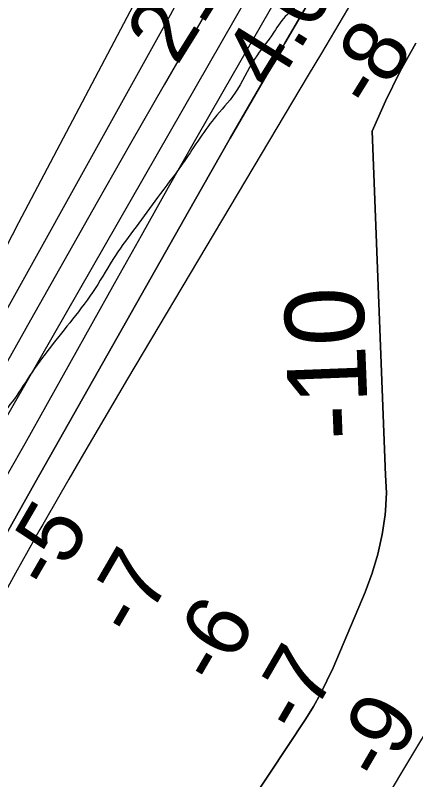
# Model space of a CAD drawing. Extents: x 3297735 to 3335592, y 670436 to 695807.
# Drawn here: x 3318935 to 3319354, y 692609 to 693409 of the extents above; entities that cross this region are included whole.
import ezdxf

# ---------------------------------------------------------------- set-up
doc = ezdxf.new("R2010")
doc.units = 0
for name, color, linetype in [('V-RIVR-EDGE', 7, 'Continuous'), ('V-RIVR-RANG', 7, 'Continuous'), ('V-TOPO-DPTH', 7, 'Continuous'), ('V-TOPO-MAJR', 7, 'Continuous'), ('V-TOPO-MINR', 7, 'Continuous'), ('V-TOPO-MINR-IDEN', 7, 'Continuous'), ('V-TOPO-WATR', 7, 'Continuous')]:
    doc.layers.add(name, color=color, linetype=linetype)

msp = doc.modelspace()

# ---------------------------------------------------------------- linework, layer by layer
at = {"layer": 'V-RIVR-EDGE'}
msp.add_spline([(3319555.14, 694014.55), (3319548.52, 694002.76), (3319539.36, 693985.79), (3319509.78, 693923.27), (3319496.46, 693903), (3319479.41, 693878.17), (3319464.01, 693854.58), (3319445.27, 693818.98), (3319424.44, 693775.51), (3319406.53, 693740.74), (3319395.69, 693713), (3319386.52, 693693.13), (3319372.79, 693671.61), (3319340.34, 693621.53), (3319316.61, 693580.14), (3319295.79, 693542.89), (3319282.06, 693520.96), (3319271.65, 693502.33), (3319267.89, 693489.49), (3319259.98, 693475.83), (3319250.42, 693465.08), (3319246.25, 693454.32), (3319237.93, 693442.32), (3319231.68, 693428.65), (3319225.43, 693414.99), (3319219.61, 693410.03), (3319205.47, 693391.42), (3319185.09, 693363.28), (3319164.7, 693327.69), (3319143.08, 693301.21), (3319109.39, 693253.21), (3319083.6, 693218.46), (3319061.14, 693187.85), (3319039.52, 693157.64), (3319018.29, 693123.29), (3318994.59, 693091.02), (3318949.68, 693031.86), (3318931.37, 693004.55), (3318913.08, 692981.38), (3318902.25, 692962.76), (3318892.68, 692944.55), (3318876.03, 692916.4), (3318861.86, 692887.84), (3318841.46, 692848.51), (3318822.29, 692807.53), (3318806.46, 692774.41), (3318803.1, 692758.66), (3318804.31, 692744.98), (3318808.02, 692734.61), (3318808.84, 692730.46), (3318817.11, 692725.47), (3318826.63, 692719.23), (3318832.83, 692713), (3318835.72, 692705.53), (3318835.27, 692692.27), (3318829.85, 692681.5), (3318819.88, 692669.09), (3318809.47, 692651.3), (3318783.24, 692602.87), (3318768.67, 692580.52), (3318760.79, 692575.98), (3318753.73, 692573.1), (3318747.11, 692573.94), (3318739.24, 692579.76), (3318735.53, 692585.58), (3318730.56, 692588.49), (3318721.44, 692588.1), (3318700.27, 692573.64), (3318679.48, 692549.66), (3318660.76, 692522.35), (3318646.6, 692493.37), (3318637.03, 692477.64), (3318624.96, 692456.95), (3318607.08, 692434.19), (3318599.98, 692413.49), (3318583.3, 692372.49), (3318565.82, 692342.28), (3318547.09, 692313.73), (3318534.2, 692295.52), (3318512.56, 692258.69), (3318488.02, 692224.76), (3318446.4, 692155.23), (3318418.11, 692112.61), (3318397.31, 692084.47), (3318386.91, 692066.68), (3318376.5, 692048.05), (3318354.44, 692011.22), (3318333.22, 691976.45), (3318316.13, 691940.02), (3318301.57, 691917.67), (3318275.38, 691884.99), (3318265.81, 691873), (3318250.82, 691844.85), (3318236.64, 691808.41), (3318222.07, 691781.09), (3318194.96, 691714.01), (3318179.96, 691684.2), (3318162.07, 691654.82), (3318140.84, 691619.64), (3318130.44, 691603.92), (3318120.89, 691595.24), (3318105.09, 691577.87), (3318090.12, 691558.42), (3318067.68, 691532.37), (3318043.56, 691501.75), (3318020.26, 691465.75), (3317998.21, 691433.06), (3317973.66, 691392.92), (3317962.42, 691371.81), (3317929.95, 691315.1), (3317907.9, 691282.41), (3317889.2, 691263.39), (3317870.48, 691238.16), (3317844.7, 691202.99), (3317833.05, 691186.02), (3317808.09, 691148.78), (3317780.64, 691109.47), (3317756.1, 691076.38), (3317731.98, 691045.35), (3317684.57, 690978.73), (3317668.76, 690954.73), (3317646.3, 690922.04), (3317635.48, 690907.15), (3317629.25, 690900.53), (3317620.1, 690889.36), (3317608.46, 690874.47), (3317601.4, 690867.03), (3317592.67, 690860.42), (3317585.59, 690845.93), (3317576.86, 690836), (3317565.64, 690821.11), (3317549.42, 690801.25), (3317522.4, 690767.75), (3317502.45, 690745), (3317489.97, 690727.62), (3317482.47, 690713.55), (3317479.54, 690701.12), (3317475.78, 690689.94), (3317474.94, 690683.31), (3317467.87, 690674.21), (3317451.65, 690653.94), (3317427.54, 690622.91), (3317406.33, 690593.95), (3317381.8, 690564.58), (3317328.18, 690504.62), (3317308.23, 690483.11), (3317290.78, 690466.16), (3317272.5, 690446.31), (3317248.81, 690422.74), (3317230.94, 690402.48), (3317202.23, 690356.54), (3317170.21, 690314.34), (3317129.47, 690266.36), (3317099.12, 690227.48), (3317085.82, 690212.59), (3317074.19, 690204.33), (3317063.38, 690189.85), (3317045.08, 690163.78), (3317020.95, 690128.61), (3316996.82, 690093.85), (3316970.63, 690059.1), (3316926.98, 690008.23), (3316891.65, 689970.6), (3316861.71, 689930.05), (3316828.03, 689887.86), (3316809.31, 689860.13), (3316797.25, 689841.93), (3316783.53, 689825.38), (3316737.37, 689762.08), (3316714.9, 689728.98), (3316681.64, 689687.61), (3316661.69, 689665.69), (3316647.97, 689646.66), (3316619.68, 689606.11), (3316602.63, 689581.28), (3316583.49, 689551.9), (3316563.93, 689519.62), (3316547.71, 689499.35), (3316541.89, 689491.9), (3316538.57, 689488.6), (3316532.31, 689474.1), (3316523.16, 689461.28), (3316509.03, 689445.15), (3316500.29, 689431.49), (3316493.22, 689419.9), (3316485.73, 689407.9), (3316486.11, 689397.12), (3316486.48, 689375.57), (3316487.29, 689371.01), (3316491.44, 689370.17), (3316493.5, 689366.43), (3316494.29, 689352.75), (3316496.75, 689341.56), (3316502.54, 689336.57), (3316504.2, 689334.08), (3316504.18, 689328.69), (3316501.27, 689325.8), (3316488.83, 689321.27), (3316487.17, 689319.61), (3316487.16, 689316.71), (3316492.96, 689316.7), (3316502.08, 689318.33), (3316508.3, 689318.32), (3316513.27, 689314.99), (3316516.58, 689314.98), (3316524.87, 689314.55), (3316535.62, 689303.33), (3316544.71, 689293.36), (3316545.54, 689290.04), (3316543.46, 689287.97), (3316525.66, 689296.72), (3316509.92, 689304.22), (3316502.06, 689307.14), (3316490.45, 689308.41), (3316482.58, 689308.02), (3316478.02, 689308.03), (3316473.47, 689311.77), (3316449.46, 689323.85), (3316424.59, 689324.74), (3316401.79, 689323.14), (3316381.47, 689318.22), (3316366.54, 689316.18), (3316352.85, 689311.24), (3316334.16, 689295.54), (3316302.2, 689277.79), (3316275.21, 689257.14), (3316266.49, 689249.28), (3316249.02, 689224.04), (3316230.28, 689191.76), (3316217.78, 689162.78), (3316200.69, 689125.93), (3316182.37, 689092.82), (3316162.8, 689054.73), (3316141.17, 689024.94), (3316114.57, 688996.41), (3316081.77, 688971.62), (3316036.89, 688926.14), (3316007.39, 688897.61), (3315987.04, 688880.67), (3315970.01, 688865.79), (3315959.63, 688858.77), (3315957.13, 688852.14), (3315955.46, 688848.42), (3315953.91, 688835.53)], degree=3, dxfattribs=at)
at = {"layer": 'V-TOPO-DPTH'}
for points in [[(3319397.53, 693802.93), (3319208.57, 693481.24), (3319197.61, 693462.51), (3319186.68, 693443.76), (3319175.8, 693424.98), (3319164.96, 693406.17), (3318890.81, 692929.09), (3318889.57, 692926.93), (3318887.11, 692922.6), (3318885.89, 692920.44), (3318883.86, 692916.84), (3318883.24, 692915.73), (3318881.62, 692912.8), (3318879.81, 692909.49), (3318878.9, 692907.83), (3318878, 692906.18), (3318861.29, 692875.47), (3318852.04, 692858.46), (3318842.79, 692841.44), (3318833.53, 692824.43), (3318824.28, 692807.42), (3318495.08, 692202.06)], [(3318762.29, 692573.01), (3318806.07, 692650.9), (3318849.52, 692728.97), (3318916.57, 692850.34), (3318926.28, 692867.85), (3318936.02, 692885.34), (3318945.82, 692902.8), (3318955.65, 692920.23), (3319122.05, 693214.3), (3319140.91, 693247.5), (3319159.83, 693280.66), (3319178.85, 693313.76), (3319197.95, 693346.82), (3319217.11, 693379.84), (3319236.3, 693412.85), (3319255.52, 693445.83), (3319274.77, 693478.8), (3319305.8, 693531.86), (3319340.53, 693591.37), (3319375.22, 693650.92)], [(3318762.29, 692573.01), (3318806.07, 692650.9), (3318849.52, 692728.97), (3318916.57, 692850.34), (3318926.28, 692867.85), (3318936.02, 692885.34), (3318945.82, 692902.8), (3318955.65, 692920.23), (3319122.05, 693214.3), (3319140.91, 693247.5), (3319159.83, 693280.66), (3319178.85, 693313.76), (3319197.95, 693346.82), (3319217.11, 693379.84), (3319236.3, 693412.85), (3319255.52, 693445.83), (3319274.77, 693478.8), (3319305.8, 693531.86), (3319340.53, 693591.37), (3319375.22, 693650.92)], [(3319143.8, 692528.91), (3319238.82, 692672.79), (3319246.83, 692685.67), (3319254.34, 692698.82), (3319261.12, 692712.36), (3319267.41, 692726.16), (3319300.94, 692805.49), (3319308.26, 692825.15), (3319314.4, 692845.12), (3319318.79, 692865.55), (3319322.01, 692886.29), (3319322.5, 692890.71), (3319323.27, 692909.31), (3319322.38, 692927.72), (3319308.3, 693288.04), (3319322.36, 693319.33), (3319337.46, 693350.07), (3319354.14, 693379.99)], [(3319354.14, 693379.99), (3319337.46, 693350.07), (3319322.36, 693319.33), (3319308.3, 693288.04), (3319322.38, 692927.72), (3319323.27, 692909.31), (3319322.5, 692890.71), (3319322.01, 692886.29), (3319318.79, 692865.55), (3319314.4, 692845.12), (3319308.26, 692825.15), (3319300.94, 692805.49), (3319267.41, 692726.16), (3319261.12, 692712.36), (3319254.34, 692698.82), (3319246.83, 692685.67), (3319238.82, 692672.79), (3319143.8, 692528.91)]]:
    msp.add_lwpolyline(points, dxfattribs=at)
at = {"layer": 'V-TOPO-MAJR'}
msp.add_lwpolyline([(3319313.56, 693852.85), (3319280.55, 693798.62), (3319123.25, 693537.44), (3319111.55, 693517.64), (3319100.09, 693497.72), (3319088.97, 693477.61), (3319078.07, 693457.37), (3318938.07, 693191.84), (3318917.38, 693152.67), (3318896.66, 693113.51), (3318875.91, 693074.37), (3318855.12, 693035.25), (3318822, 692973.01), (3318817.73, 692965.03), (3318813.44, 692957.06), (3318809.11, 692949.11), (3318804.75, 692941.17), (3318509.85, 692406.6)], dxfattribs=at)
at = {"layer": 'V-TOPO-MINR'}
for points in [[(3319458.23, 694014.45), (3319181.56, 693556.63), (3319173.57, 693543.32), (3319165.62, 693529.99), (3319157.74, 693516.62), (3319149.9, 693503.22), (3319136.82, 693480.7), (3319135.57, 693478.53), (3319133.09, 693474.19), (3319131.87, 693472.01), (3319119.33, 693449.58), (3319111.85, 693436.18), (3319104.37, 693422.78), (3319096.9, 693409.37), (3319089.43, 693395.96), (3318863.75, 692990.42), (3318850.58, 692966.73), (3318837.43, 692943.03), (3318824.29, 692919.32), (3318811.17, 692895.6), (3318709.69, 692711.94), (3318656.45, 692615.16), (3318603.44, 692518.24)], [(3319397.53, 693802.93), (3319208.57, 693481.24), (3319197.61, 693462.51), (3319186.68, 693443.76), (3319175.8, 693424.98), (3319164.96, 693406.17), (3318890.81, 692929.09), (3318889.57, 692926.93), (3318887.11, 692922.6), (3318885.89, 692920.44), (3318883.86, 692916.84), (3318883.24, 692915.73), (3318881.62, 692912.8), (3318879.81, 692909.49), (3318878.9, 692907.83), (3318878, 692906.18), (3318861.29, 692875.47), (3318852.04, 692858.46), (3318842.79, 692841.44), (3318833.53, 692824.43), (3318824.28, 692807.42), (3318495.08, 692202.06)], [(3319364.99, 693805.47), (3319198.47, 693522.45), (3319179.99, 693490.94), (3319161.57, 693459.39), (3319143.25, 693427.79), (3319124.99, 693396.16), (3319090.7, 693336.53), (3319055.43, 693275), (3319020.29, 693213.4), (3318985.34, 693151.69), (3318950.51, 693089.91), (3318873.91, 692953.53), (3318867.2, 692941.53), (3318860.49, 692929.53), (3318853.82, 692917.51), (3318847.17, 692905.48), (3318801.31, 692822.39), (3318771.81, 692768.77), (3318742.39, 692715.1), (3318713.11, 692661.36), (3318683.92, 692607.57)], [(3319504.71, 693794.02), (3319296.15, 693438.76), (3319282.54, 693415.63), (3319268.9, 693392.52), (3319255.22, 693369.44), (3319241.51, 693346.38), (3319052.26, 693028.68), (3319036.75, 693002.52), (3319021.33, 692976.33), (3319006.01, 692950.06), (3318990.77, 692923.75), (3318966.24, 692881.19), (3318963.34, 692876.12), (3318960.45, 692871.05), (3318957.59, 692865.95), (3318954.75, 692860.85), (3318934.95, 692825.09), (3318922.15, 692802.14), (3318909.26, 692779.24), (3318896.22, 692756.42), (3318883.08, 692733.66), (3318534.83, 692134.49)], [(3319358.13, 693682.81), (3319333.43, 693640.56), (3319308.71, 693598.31), (3319283.96, 693556.09), (3319259.18, 693513.88), (3319217.85, 693443.52), (3319213.74, 693436.49), (3319209.64, 693429.45), (3319205.56, 693422.4), (3319201.49, 693415.34), (3319152.07, 693329.2), (3319123.39, 693279.02), (3319094.82, 693228.78), (3319066.4, 693178.45), (3319038.1, 693128.05), (3318944.49, 692960.75), (3318927.59, 692930.46), (3318910.73, 692900.14), (3318893.95, 692869.78), (3318877.22, 692839.4), (3318695.95, 692509.33)], [(3319354.14, 693379.99), (3319337.46, 693350.07), (3319322.36, 693319.33), (3319308.3, 693288.04), (3319322.38, 692927.72), (3319323.27, 692909.31), (3319322.5, 692890.71), (3319322.01, 692886.29), (3319318.79, 692865.55), (3319314.4, 692845.12), (3319308.26, 692825.15), (3319300.94, 692805.49), (3319267.41, 692726.16), (3319261.12, 692712.36), (3319254.34, 692698.82), (3319246.83, 692685.67), (3319238.82, 692672.79), (3319143.8, 692528.91)], [(3319368.17, 692664.9), (3319353.67, 692640.85), (3319339.26, 692616.74), (3319324.91, 692592.6)]]:
    msp.add_lwpolyline(points, dxfattribs=at)
at = {"layer": 'V-TOPO-WATR'}
msp.add_lwpolyline([(3319375.22, 693650.92), (3319340.53, 693591.37), (3319305.8, 693531.86), (3319274.77, 693478.8), (3319255.52, 693445.83), (3319236.3, 693412.85), (3319217.11, 693379.84), (3319197.95, 693346.82), (3319178.85, 693313.76), (3319159.83, 693280.66), (3319140.91, 693247.5), (3319122.05, 693214.3), (3318955.65, 692920.23), (3318945.82, 692902.8), (3318936.02, 692885.34), (3318926.28, 692867.85), (3318916.57, 692850.34), (3318849.52, 692728.97), (3318806.07, 692650.9), (3318762.29, 692573.01)], dxfattribs=at)

# ---------------------------------------------------------------- texts
at = {"layer": 'V-RIVR-RANG'}
for s, rotation, p in [('21.4', 57.93833, (3319103.93, 693355.35)), ('4.0', 58.22036, (3319205.37, 693328.1)), ('-8', 58.22036, (3319310.53, 693307.96)), ('-5', 59.81142, (3318973.85, 692804.32)), ('-7', 59.81142, (3319060.82, 692754.95)), ('-6', 59.81142, (3319147.27, 692704.69)), ('-7', 59.81142, (3319233.44, 692653.96)), ('-9', 59.81142, (3319320.03, 692603.93))]:
    msp.add_text(s, height=67, rotation=rotation, dxfattribs=at).set_placement(p)
at = {"layer": 'V-TOPO-MINR-IDEN'}
msp.add_text('-10', height=83, rotation=92.23718, dxfattribs=at).set_placement((3319304.95, 692965.98))

doc.saveas('drawing.dxf')
